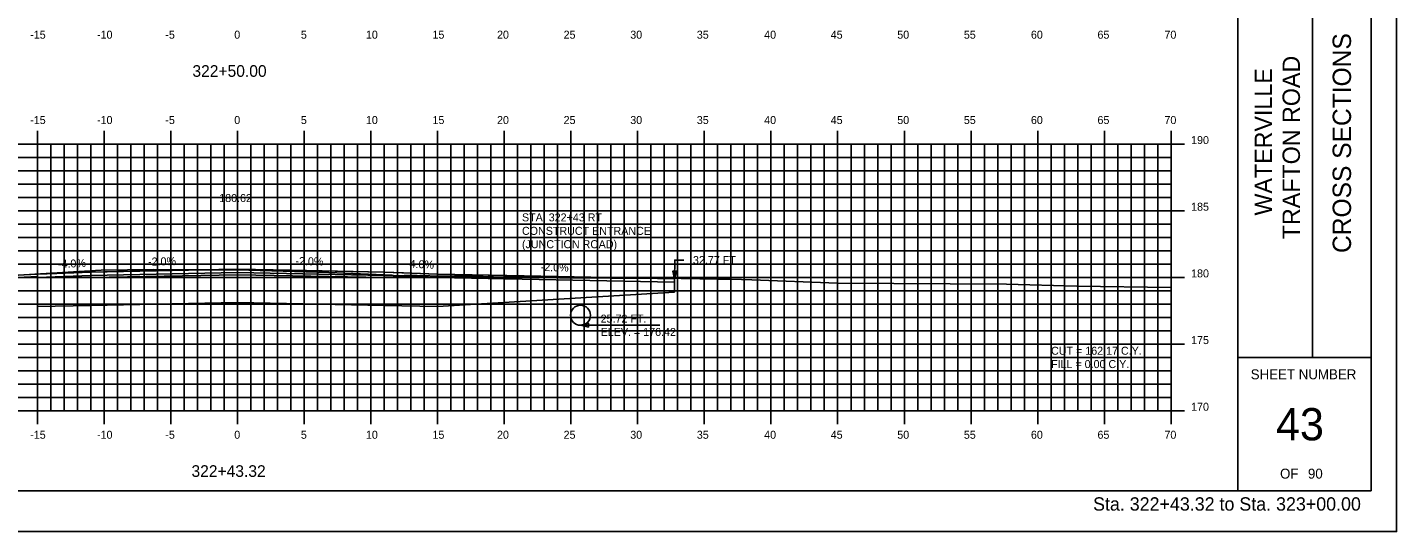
# Model space of a CAD drawing. Extents: x 1140094 to 1140264, y 608981 to 609091.
# Drawn here: x 1140161 to 1140263.6, y 608981.3 to 609019.1 of the extents above; entities that cross this region are included whole.
import ezdxf

# ---------------------------------------------------------------- set-up
doc = ezdxf.new("R2010")
doc.units = 0
for name, color, linetype in [('ANNOTATION', 7, 'Continuous'), ('BORDER', 7, 'Continuous'), ('D_Drainage_Culvert', 7, 'Continuous'), ('D_Roadway_Centerline', 7, 'Continuous'), ('D_Roadway_Centerline_Text', 7, 'Continuous'), ('D_Roadway_Edge_Shoulder', 7, 'Continuous'), ('D_Roadway_Edge_TW', 7, 'Continuous'), ('D_Roadway_Pavement', 7, 'Continuous'), ('D_Roadway_SubGrade', 7, 'Continuous'), ('D_Text_Standard', 7, 'Continuous'), ('H_V ANNOTATION', 7, 'Continuous'), ('HIGHWAY_TITLE', 7, 'Continuous'), ('MAJOR', 7, 'Continuous'), ('MINOR', 7, 'Continuous'), ('PLOT BOUNDARY', 7, 'Continuous'), ('S_Roadway_Centerline', 7, 'Continuous')]:
    doc.layers.add(name, color=color, linetype=linetype)

msp = doc.modelspace()

# ---------------------------------------------------------------- linework, layer by layer
msp.add_lwpolyline([(1140161.73, 609000.58), (1140161.73, 609000.58), (1140161.73, 609000.58), (1140163.19, 609000.64), (1140165.73, 609000.74), (1140169.75, 609000.82), (1140176.73, 609000.96), (1140180.75, 609000.88), (1140187.73, 609000.74), (1140189.19, 609000.68), (1140191.73, 609000.58), (1140198.22, 609000.45), (1140209.5, 609000.22)])
at = {"layer": 'BORDER'}
for p, q in [((1140251.73, 608984.34), (1140251.73, 609089.34)), ((1140257.32, 608994.34), (1140257.32, 609029.34)), ((1140251.73, 608994.34), (1140261.73, 608994.34))]:
    msp.add_line(p, q, dxfattribs=at)
msp.add_lwpolyline([(1140101.73, 608984.34), (1140261.73, 608984.34), (1140261.73, 609089.34), (1140101.73, 609089.34)], close=True, dxfattribs=at)
at = {"layer": 'D_Drainage_Culvert'}
msp.add_circle((1140202.45, 608997.5), 0.75, dxfattribs=at)
at = {"layer": 'D_Roadway_Edge_Shoulder'}
for points in [[(1140161.73, 609000.58), (1140158.73, 609000.42), (1140158.74, 609000.25), (1140161.73, 609000.41)], [(1140165.73, 609000.74), (1140161.73, 609000.58), (1140161.73, 609000.33), (1140165.73, 609000.49)], [(1140187.73, 609000.74), (1140191.73, 609000.58), (1140191.73, 609000.33), (1140187.73, 609000.49)], [(1140191.73, 609000.58), (1140191.73, 609000.34), (1140209.5, 608999.98), (1140209.5, 609000.22)]]:
    msp.add_lwpolyline(points, close=True, dxfattribs=at)
at = {"layer": 'D_Roadway_Edge_TW'}
msp.add_lwpolyline([(1140165.73, 609000.49), (1140165.73, 609000.74), (1140176.73, 609000.96), (1140187.73, 609000.74), (1140187.73, 609000.49), (1140176.73, 609000.71)], close=True, dxfattribs=at)
at = {"layer": 'D_Roadway_Pavement'}
msp.add_lwpolyline([(1140165.73, 609000.32), (1140165.73, 609000.49), (1140176.73, 609000.71), (1140187.73, 609000.49), (1140187.73, 609000.32), (1140176.73, 609000.54)], close=True, dxfattribs=at)
at = {"layer": 'D_Roadway_SubGrade'}
for points in [[(1140161.73, 608999.58), (1140161.73, 608998.16), (1140165.73, 608998.24), (1140165.73, 609000.32), (1140165.73, 609000.49), (1140161.73, 609000.33), (1140161.73, 609000.58), (1140161.73, 609000.58)], [(1140165.73, 608998.24), (1140165.73, 609000.32), (1140176.73, 609000.54), (1140187.73, 609000.32), (1140187.73, 608998.24), (1140176.73, 608998.46)], [(1140209.5, 608999.22), (1140209.5, 609000.22), (1140191.73, 609000.58), (1140191.73, 609000.33), (1140187.73, 609000.49), (1140187.73, 609000.32), (1140187.73, 608998.24), (1140191.73, 608998.16)]]:
    msp.add_lwpolyline(points, close=True, dxfattribs=at)
at = {"layer": 'D_Text_Standard'}
msp.add_line((1140203.96, 608996.75), (1140208.4, 608996.75), dxfattribs=at)
for points in [[(1140209.5, 609000.22), (1140209.52, 609001.64), (1140210.2, 609001.64)], [(1140202.45, 608996.75), (1140203.28, 608996.75), (1140203.96, 608996.75)]]:
    msp.add_lwpolyline(points, dxfattribs=at)
for points in [[(1140209.5, 609000.22), (1140209.36, 609000.8), (1140209.65, 609000.8)], [(1140202.45, 608996.75), (1140203.04, 608996.9), (1140203.04, 608996.61)]]:
    msp.add_lwpolyline(points, close=True, dxfattribs=at)
at = {"layer": 'MAJOR'}
for p, q in [((1140161.73, 609011.34), (1140161.73, 609010.34)), ((1140166.73, 609011.34), (1140166.73, 609010.34)), ((1140171.73, 609011.34), (1140171.73, 609010.34)), ((1140176.73, 609011.34), (1140176.73, 609010.34)), ((1140181.73, 609011.34), (1140181.73, 609010.34)), ((1140186.73, 609011.34), (1140186.73, 609010.34)), ((1140191.73, 609011.34), (1140191.73, 609010.34)), ((1140196.73, 609011.34), (1140196.73, 609010.34)), ((1140201.73, 609011.34), (1140201.73, 609010.34)), ((1140206.73, 609011.34), (1140206.73, 609010.34)), ((1140211.73, 609011.34), (1140211.73, 609010.34)), ((1140216.73, 609011.34), (1140216.73, 609010.34)), ((1140221.73, 609011.34), (1140221.73, 609010.34)), ((1140226.73, 609011.34), (1140226.73, 609010.34)), ((1140231.73, 609011.34), (1140231.73, 609010.34)), ((1140236.73, 609011.34), (1140236.73, 609010.34)), ((1140241.73, 609011.34), (1140241.73, 609010.34)), ((1140246.73, 609011.34), (1140246.73, 609010.34)), ((1140106.73, 609010.34), (1140246.73, 609010.34)), ((1140106.73, 609010.34), (1140246.73, 609010.34)), ((1140161.73, 608990.34), (1140161.73, 609010.34)), ((1140166.73, 608990.34), (1140166.73, 609010.34)), ((1140171.73, 608990.34), (1140171.73, 609010.34)), ((1140176.73, 608990.34), (1140176.73, 609010.34)), ((1140181.73, 608990.34), (1140181.73, 609010.34)), ((1140186.73, 608990.34), (1140186.73, 609010.34)), ((1140191.73, 608990.34), (1140191.73, 609010.34)), ((1140196.73, 608990.34), (1140196.73, 609010.34)), ((1140201.73, 608990.34), (1140201.73, 609010.34)), ((1140206.73, 608990.34), (1140206.73, 609010.34)), ((1140211.73, 608990.34), (1140211.73, 609010.34)), ((1140216.73, 608990.34), (1140216.73, 609010.34)), ((1140221.73, 608990.34), (1140221.73, 609010.34)), ((1140226.73, 608990.34), (1140226.73, 609010.34)), ((1140231.73, 608990.34), (1140231.73, 609010.34)), ((1140236.73, 608990.34), (1140236.73, 609010.34)), ((1140241.73, 608990.34), (1140241.73, 609010.34)), ((1140247.73, 609010.34), (1140245.73, 609010.34)), ((1140246.73, 608990.34), (1140246.73, 609010.34)), ((1140246.73, 608990.34), (1140246.73, 609010.34)), ((1140106.73, 609005.34), (1140246.73, 609005.34)), ((1140247.73, 609005.34), (1140245.73, 609005.34)), ((1140106.73, 609000.34), (1140246.73, 609000.34)), ((1140247.73, 609000.34), (1140245.73, 609000.34)), ((1140106.73, 608995.34), (1140246.73, 608995.34)), ((1140247.73, 608995.34), (1140245.73, 608995.34)), ((1140106.73, 608990.34), (1140246.73, 608990.34)), ((1140106.73, 608990.34), (1140246.73, 608990.34)), ((1140161.73, 608989.33), (1140161.73, 608990.34)), ((1140166.73, 608989.33), (1140166.73, 608990.34)), ((1140171.73, 608989.33), (1140171.73, 608990.34)), ((1140176.73, 608989.33), (1140176.73, 608990.34)), ((1140181.73, 608989.33), (1140181.73, 608990.34)), ((1140186.73, 608989.33), (1140186.73, 608990.34)), ((1140191.73, 608989.33), (1140191.73, 608990.34)), ((1140196.73, 608989.33), (1140196.73, 608990.34)), ((1140201.73, 608989.33), (1140201.73, 608990.34)), ((1140206.73, 608989.33), (1140206.73, 608990.34)), ((1140211.73, 608989.33), (1140211.73, 608990.34)), ((1140216.73, 608989.33), (1140216.73, 608990.34)), ((1140221.73, 608989.33), (1140221.73, 608990.34)), ((1140226.73, 608989.33), (1140226.73, 608990.34)), ((1140231.73, 608989.33), (1140231.73, 608990.34)), ((1140236.73, 608989.33), (1140236.73, 608990.34)), ((1140241.73, 608989.33), (1140241.73, 608990.34)), ((1140247.73, 608990.34), (1140245.73, 608990.34)), ((1140246.73, 608989.33), (1140246.73, 608990.34))]:
    msp.add_line(p, q, dxfattribs=at)
at = {"layer": 'MINOR'}
for p, q in [((1140162.73, 608990.34), (1140162.73, 609010.34)), ((1140163.73, 608990.34), (1140163.73, 609010.34)), ((1140164.73, 608990.34), (1140164.73, 609010.34)), ((1140165.73, 608990.34), (1140165.73, 609010.34)), ((1140167.73, 608990.34), (1140167.73, 609010.34)), ((1140168.73, 608990.34), (1140168.73, 609010.34)), ((1140169.73, 608990.34), (1140169.73, 609010.34)), ((1140170.73, 608990.34), (1140170.73, 609010.34)), ((1140172.73, 608990.34), (1140172.73, 609010.34)), ((1140173.73, 608990.34), (1140173.73, 609010.34)), ((1140174.73, 608990.34), (1140174.73, 609010.34)), ((1140175.73, 608990.34), (1140175.73, 609010.34)), ((1140177.73, 608990.34), (1140177.73, 609010.34)), ((1140178.73, 608990.34), (1140178.73, 609010.34)), ((1140179.73, 608990.34), (1140179.73, 609010.34)), ((1140180.73, 608990.34), (1140180.73, 609010.34)), ((1140182.73, 608990.34), (1140182.73, 609010.34)), ((1140183.73, 608990.34), (1140183.73, 609010.34)), ((1140184.73, 608990.34), (1140184.73, 609010.34)), ((1140185.73, 608990.34), (1140185.73, 609010.34)), ((1140187.73, 608990.34), (1140187.73, 609010.34)), ((1140188.73, 608990.34), (1140188.73, 609010.34)), ((1140189.73, 608990.34), (1140189.73, 609010.34)), ((1140190.73, 608990.34), (1140190.73, 609010.34)), ((1140192.73, 608990.34), (1140192.73, 609010.34)), ((1140193.73, 608990.34), (1140193.73, 609010.34)), ((1140194.73, 608990.34), (1140194.73, 609010.34)), ((1140195.73, 608990.34), (1140195.73, 609010.34)), ((1140197.73, 608990.34), (1140197.73, 609010.34)), ((1140198.73, 608990.34), (1140198.73, 609010.34)), ((1140199.73, 608990.34), (1140199.73, 609010.34)), ((1140200.73, 608990.34), (1140200.73, 609010.34)), ((1140202.73, 608990.34), (1140202.73, 609010.34)), ((1140203.73, 608990.34), (1140203.73, 609010.34)), ((1140204.73, 608990.34), (1140204.73, 609010.34)), ((1140205.73, 608990.34), (1140205.73, 609010.34)), ((1140207.73, 608990.34), (1140207.73, 609010.34)), ((1140208.73, 608990.34), (1140208.73, 609010.34)), ((1140209.73, 608990.34), (1140209.73, 609010.34)), ((1140210.73, 608990.34), (1140210.73, 609010.34)), ((1140212.73, 608990.34), (1140212.73, 609010.34)), ((1140213.73, 608990.34), (1140213.73, 609010.34)), ((1140214.73, 608990.34), (1140214.73, 609010.34)), ((1140215.73, 608990.34), (1140215.73, 609010.34)), ((1140217.73, 608990.34), (1140217.73, 609010.34)), ((1140218.73, 608990.34), (1140218.73, 609010.34)), ((1140219.73, 608990.34), (1140219.73, 609010.34)), ((1140220.73, 608990.34), (1140220.73, 609010.34)), ((1140222.73, 608990.34), (1140222.73, 609010.34)), ((1140223.73, 608990.34), (1140223.73, 609010.34)), ((1140224.73, 608990.34), (1140224.73, 609010.34)), ((1140225.73, 608990.34), (1140225.73, 609010.34)), ((1140227.73, 608990.34), (1140227.73, 609010.34)), ((1140228.73, 608990.34), (1140228.73, 609010.34)), ((1140229.73, 608990.34), (1140229.73, 609010.34)), ((1140230.73, 608990.34), (1140230.73, 609010.34)), ((1140232.73, 608990.34), (1140232.73, 609010.34)), ((1140233.73, 608990.34), (1140233.73, 609010.34)), ((1140234.73, 608990.34), (1140234.73, 609010.34)), ((1140235.73, 608990.34), (1140235.73, 609010.34)), ((1140237.73, 608990.34), (1140237.73, 609010.34)), ((1140238.73, 608990.34), (1140238.73, 609010.34)), ((1140239.73, 608990.34), (1140239.73, 609010.34)), ((1140240.73, 608990.34), (1140240.73, 609010.34)), ((1140242.73, 608990.34), (1140242.73, 609010.34)), ((1140243.73, 608990.34), (1140243.73, 609010.34)), ((1140244.73, 608990.34), (1140244.73, 609010.34)), ((1140245.73, 608990.34), (1140245.73, 609010.34)), ((1140106.73, 609009.34), (1140246.73, 609009.34)), ((1140246.73, 609009.34), (1140245.73, 609009.34)), ((1140106.73, 609008.34), (1140246.73, 609008.34)), ((1140106.73, 609007.34), (1140246.73, 609007.34)), ((1140246.73, 609008.34), (1140245.73, 609008.34)), ((1140246.73, 609007.34), (1140245.73, 609007.34)), ((1140106.73, 609006.34), (1140246.73, 609006.34)), ((1140246.73, 609006.34), (1140245.73, 609006.34)), ((1140106.73, 609004.34), (1140246.73, 609004.34)), ((1140246.73, 609004.34), (1140245.73, 609004.34)), ((1140106.73, 609003.34), (1140246.73, 609003.34)), ((1140246.73, 609003.34), (1140245.73, 609003.34)), ((1140106.73, 609002.34), (1140246.73, 609002.34)), ((1140246.73, 609002.34), (1140245.73, 609002.34)), ((1140106.73, 609001.34), (1140246.73, 609001.34)), ((1140246.73, 609001.34), (1140245.73, 609001.34)), ((1140106.73, 608999.34), (1140246.73, 608999.34)), ((1140246.73, 608999.34), (1140245.73, 608999.34)), ((1140106.73, 608998.34), (1140246.73, 608998.34)), ((1140246.73, 608998.34), (1140245.73, 608998.34)), ((1140106.73, 608997.34), (1140246.73, 608997.34)), ((1140246.73, 608997.34), (1140245.73, 608997.34)), ((1140106.73, 608996.34), (1140246.73, 608996.34)), ((1140246.73, 608996.34), (1140245.73, 608996.34)), ((1140106.73, 608994.34), (1140246.73, 608994.34)), ((1140246.73, 608994.34), (1140245.73, 608994.34)), ((1140106.73, 608993.34), (1140246.73, 608993.34)), ((1140246.73, 608993.34), (1140245.73, 608993.34)), ((1140106.73, 608992.34), (1140246.73, 608992.34)), ((1140246.73, 608992.34), (1140245.73, 608992.34)), ((1140106.73, 608991.34), (1140246.73, 608991.34)), ((1140246.73, 608991.34), (1140245.73, 608991.34))]:
    msp.add_line(p, q, dxfattribs=at)
at = {"layer": 'PLOT BOUNDARY'}
msp.add_lwpolyline([(1140093.64, 608981.28), (1140263.64, 608981.28), (1140263.64, 609091.28), (1140093.64, 609091.28)], close=True, dxfattribs=at)
at = {"layer": 'S_Roadway_Centerline'}
msp.add_lwpolyline([(1140152.84, 609000.06), (1140166.52, 609000.89), (1140170.45, 609000.92), (1140177.57, 609000.88), (1140183.57, 609000.7), (1140188.33, 609000.5), (1140188.55, 609000.46), (1140189.23, 609000.47), (1140189.78, 609000.48), (1140190.2, 609000.48), (1140191.15, 609000.46), (1140193.84, 609000.44), (1140194.66, 609000.42), (1140195.14, 609000.41), (1140195.93, 609000.39), (1140198.48, 609000.35), (1140199.56, 609000.33), (1140200.87, 609000.31), (1140201.86, 609000.3), (1140204.68, 609000.29), (1140206.56, 609000.28), (1140208.59, 609000.27), (1140212.8, 609000.21), (1140213.75, 609000.2), (1140215.3, 609000.16), (1140221.73, 608999.91), (1140234.39, 608999.83), (1140239.66, 608999.68), (1140246.73, 608999.59)], dxfattribs=at)

# ---------------------------------------------------------------- texts
at = {"layer": 'ANNOTATION'}
for s, p in [('STA. 322+43 RT', (1140198.06, 609004.54)), ('CONSTRUCT ENTRANCE', (1140198.06, 609003.53)), ('(JUNCTION ROAD)', (1140198.06, 609002.53))]:
    msp.add_text(s, height=0.6, dxfattribs=at).set_placement(p)
for s, rotation, p in [('-4.0%', 2.2906, (1140163.28, 609001.04)), ('-2.0%', 1.1458, (1140170.03, 609001.22)), ('-2.0%', 358.8542, (1140181.07, 609001.27)), ('-4.0%', 357.7094, (1140189.36, 609001.07)), ('-2.0%', 358.8542, (1140199.46, 609000.82))]:
    msp.add_text(s, height=0.6, rotation=rotation, dxfattribs=at).set_placement(p)
at = {"layer": 'BORDER'}
msp.add_text('CROSS SECTIONS', height=1.3779, rotation=90, dxfattribs=at).set_placement((1140260.22, 609002.17))
for s, height, p in [('SHEET NUMBER', 0.7453, (1140252.7, 608992.7)), ('43', 2.419, (1140254.59, 608988.12)), ('OF', 0.745, (1140254.9, 608985.25)), ('90', 0.745, (1140256.99, 608985.25))]:
    msp.add_text(s, height=height, dxfattribs=at).set_placement(p)
at = {"layer": 'D_Roadway_Centerline'}
for s, p in [('C', (1140176.73, 609000.96)), ('L', (1140176.73, 609000.95))]:
    msp.add_text(s, height=0.0146, dxfattribs=at).set_placement(p)
at = {"layer": 'D_Roadway_Centerline_Text'}
msp.add_text('180.62', height=0.6, dxfattribs=at).set_placement((1140175.36, 609005.99))
at = {"layer": 'D_Text_Standard'}
for s, p in [('32.77 FT', (1140210.88, 609001.34)), ('25.72 FT.', (1140203.96, 608996.95)), ('ELEV. = 176.42', (1140203.96, 608995.95)), ('CUT = 162.17 C.Y.', (1140237.73, 608994.54)), ('FILL = 0.00 C.Y.', (1140237.73, 608993.54))]:
    msp.add_text(s, height=0.6, dxfattribs=at).set_placement(p)
at = {"layer": 'H_V ANNOTATION'}
for s, height, p in [('-15', 0.6, (1140161.19, 609018.24)), ('-10', 0.6, (1140166.2, 609018.24)), ('-5', 0.6, (1140171.32, 609018.24)), ('0', 0.6, (1140176.49, 609018.24)), ('5', 0.6, (1140181.48, 609018.24)), ('10', 0.6, (1140186.36, 609018.24)), ('15', 0.6, (1140191.35, 609018.24)), ('20', 0.6, (1140196.19, 609018.24)), ('25', 0.6, (1140201.18, 609018.24)), ('30', 0.6, (1140206.18, 609018.24)), ('35', 0.6, (1140211.17, 609018.24)), ('40', 0.6, (1140216.22, 609018.24)), ('45', 0.6, (1140221.21, 609018.24)), ('50', 0.6, (1140226.2, 609018.24)), ('55', 0.6, (1140231.19, 609018.24)), ('60', 0.6, (1140236.22, 609018.24)), ('65', 0.6, (1140241.21, 609018.24)), ('70', 0.6, (1140246.23, 609018.24)), ('322+50.00', 0.875, (1140173.35, 609015.38)), ('-15', 0.6, (1140161.19, 609011.84)), ('-10', 0.6, (1140166.2, 609011.84)), ('-5', 0.6, (1140171.32, 609011.84)), ('0', 0.6, (1140176.49, 609011.84)), ('5', 0.6, (1140181.48, 609011.84)), ('10', 0.6, (1140186.36, 609011.84)), ('15', 0.6, (1140191.35, 609011.84)), ('20', 0.6, (1140196.19, 609011.84)), ('25', 0.6, (1140201.18, 609011.84)), ('30', 0.6, (1140206.18, 609011.84)), ('35', 0.6, (1140211.17, 609011.84)), ('40', 0.6, (1140216.22, 609011.84)), ('45', 0.6, (1140221.21, 609011.84)), ('50', 0.6, (1140226.2, 609011.84)), ('55', 0.6, (1140231.19, 609011.84)), ('60', 0.6, (1140236.22, 609011.84)), ('65', 0.6, (1140241.21, 609011.84)), ('70', 0.6, (1140246.23, 609011.84)), ('190', 0.6, (1140248.23, 609010.34)), ('185', 0.6, (1140248.23, 609005.34)), ('180', 0.6, (1140248.23, 609000.34)), ('175', 0.6, (1140248.23, 608995.34)), ('170', 0.6, (1140248.23, 608990.34)), ('-15', 0.6, (1140161.19, 608988.24)), ('-10', 0.6, (1140166.2, 608988.24)), ('-5', 0.6, (1140171.32, 608988.24)), ('0', 0.6, (1140176.49, 608988.24)), ('5', 0.6, (1140181.48, 608988.24)), ('10', 0.6, (1140186.36, 608988.24)), ('15', 0.6, (1140191.35, 608988.24)), ('20', 0.6, (1140196.19, 608988.24)), ('25', 0.6, (1140201.18, 608988.24)), ('30', 0.6, (1140206.18, 608988.24)), ('35', 0.6, (1140211.17, 608988.24)), ('40', 0.6, (1140216.22, 608988.24)), ('45', 0.6, (1140221.21, 608988.24)), ('50', 0.6, (1140226.2, 608988.24)), ('55', 0.6, (1140231.19, 608988.24)), ('60', 0.6, (1140236.22, 608988.24)), ('65', 0.6, (1140241.21, 608988.24)), ('70', 0.6, (1140246.23, 608988.24)), ('322+43.32', 0.875, (1140173.28, 608985.38)), ('Sta. 322+43.32 to Sta. 323+00.00', 1.0002, (1140240.88, 608982.85))]:
    msp.add_text(s, height=height, dxfattribs=at).set_placement(p)
at = {"layer": 'HIGHWAY_TITLE'}
for s, height, p in [('TRAFTON ROAD', 1.3043, (1140256.39, 609003.2)), ('WATERVILLE', 1.304, (1140254.3, 609004.98))]:
    msp.add_text(s, height=height, rotation=90, dxfattribs=at).set_placement(p)
at = {"layer": 'S_Roadway_Centerline'}
for s, p in [('C', (1140177.57, 609000.88)), ('L', (1140177.57, 609000.87))]:
    msp.add_text(s, height=0.0146, dxfattribs=at).set_placement(p)

doc.saveas('drawing.dxf')
